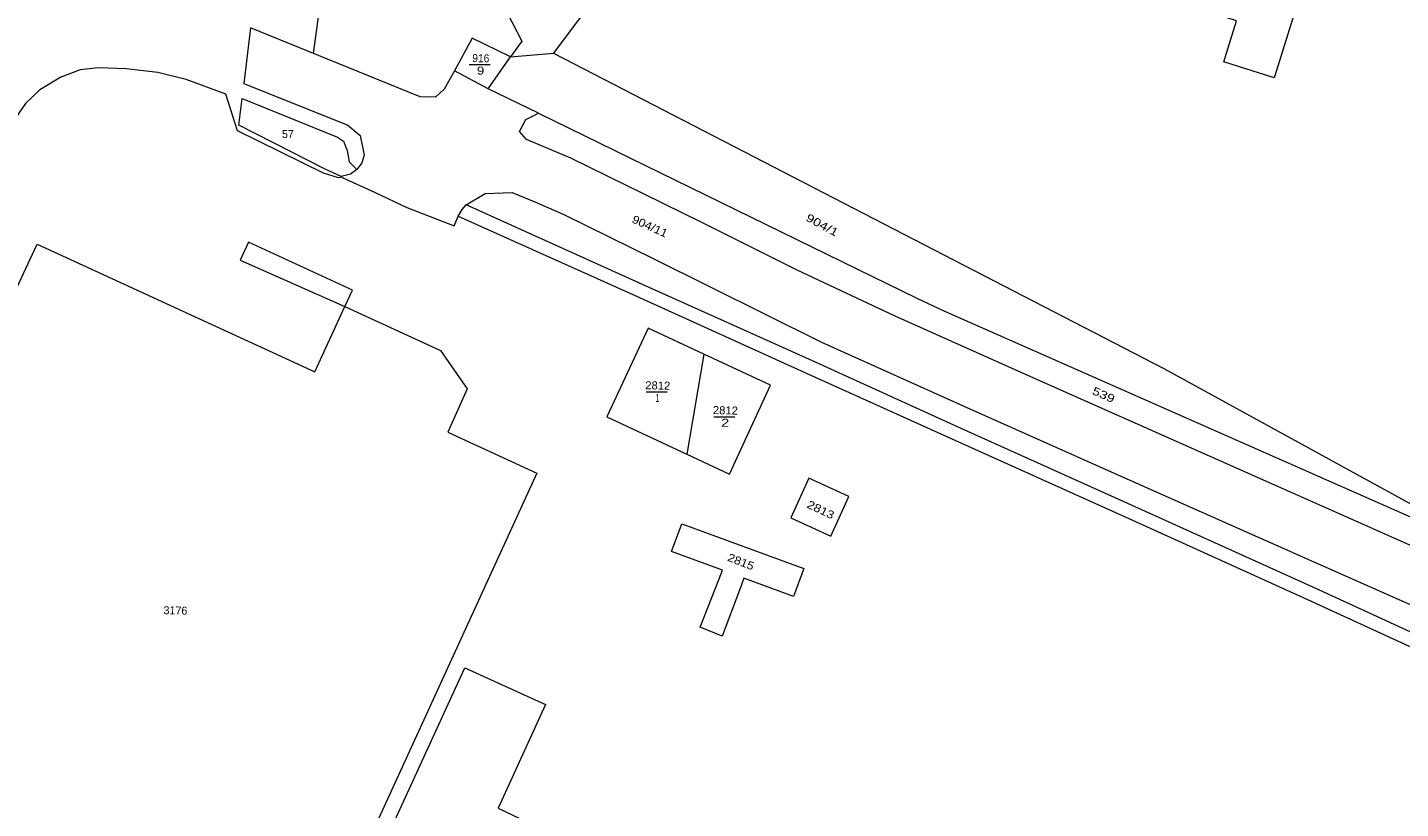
# Model space of a CAD drawing. Extents: x -843400 to -842830, y -1002860 to -1002082.
# Drawn here: x -843269.1 to -843097.6, y -1002620.7 to -1002523 of the extents above; entities that cross this region are included whole.
import ezdxf
from ezdxf.enums import TextEntityAlignment as Align

# ---------------------------------------------------------------- set-up
doc = ezdxf.new("R2010")
doc.units = 0
doc.header["$LTSCALE"] = 0.4
for name, color, linetype, lineweight in [('32', 7, 'Continuous', 13), ('34', 7, 'Continuous', 13), ('35', 7, 'Continuous', 13), ('36', 7, 'Continuous', 13), ('38', 7, 'Continuous', 13), ('43', 7, 'Continuous', 13)]:
    doc.layers.add(name, color=color, linetype=linetype, lineweight=lineweight)

msp = doc.modelspace()

# ---------------------------------------------------------------- linework, layer by layer
at = {"layer": '32'}
for points in [[(-843233.392, -1002526.274), (-843231.55, -1002512.84), (-843228.02, -1002494.21), (-843211.7, -1002440.09), (-843186.05, -1002387.15), (-843223.42, -1002493.62), (-843207.38, -1002524.72), (-843208.79, -1002526.68)], [(-843074.76, -1002421.55), (-843135.09, -1002501.71), (-843167.05, -1002477.66), (-843203.39, -1002526.24)], [(-843205.3, -1002533.74), (-843211.56, -1002530.68), (-843215.76, -1002528.45), (-843217.07, -1002530.74), (-843218.13, -1002531.75), (-843220.05, -1002531.68), (-843231.64, -1002526.99), (-843241.26, -1002523.06), (-843242.09, -1002530.04), (-843229.1, -1002535.25), (-843227.54, -1002536.54), (-843227.04, -1002539), (-843227.35, -1002539.95), (-843227.97, -1002540.79)], [(-843208.79, -1002526.68), (-843213.55, -1002524.36), (-843215.76, -1002528.45)], [(-843211.56, -1002530.68), (-843208.79, -1002526.68), (-843203.39, -1002526.24), (-843127.17, -1002565.66), (-843092.3, -1002584.79), (-843080.9, -1002591.04)], [(-843229.79, -1002541.74), (-843230.26, -1002541.8), (-843232.13, -1002541.23), (-843242.89, -1002535.94), (-843244.35, -1002531.36), (-843249.31, -1002529.54), (-843252.84, -1002528.66), (-843256.77, -1002528.18), (-843260.3, -1002528.06), (-843262.55, -1002528.32), (-843264.95, -1002529.25), (-843267.58, -1002530.82), (-843269.35, -1002532.51), (-843271.05, -1002534.95), (-843272.73, -1002537.9), (-843273.74, -1002539.98), (-843276.02, -1002546.1), (-843276.39, -1002546.03), (-843279.4, -1002552.38), (-843279.629, -1002552.744)], [(-843229.94, -1002541.67), (-843229.79, -1002541.763), (-843225.79, -1002543.62), (-843221.75, -1002545.52), (-843215.83, -1002547.82), (-843215.33, -1002546.59), (-843214.8, -1002545.76), (-843214.31, -1002545.2)], [(-843215.33, -1002546.59), (-843193.12, -1002556.57), (-843172, -1002566.13), (-843153.26, -1002574.59), (-843132, -1002584.19), (-843109.23, -1002594.52), (-843093.46, -1002601.76), (-843073.75, -1002610.86), (-843049.84, -1002621.77), (-843030.19, -1002630.96), (-843005, -1002642.63), (-842985.15, -1002651.86), (-842980.77, -1002653.89), (-842955.35, -1002665.65), (-842942.73, -1002671.51), (-842941.29, -1002671.85), (-842940.287, -1002671.376)]]:
    msp.add_lwpolyline(points, dxfattribs=at)
at = {"layer": '34'}
msp.add_line((-843213.928, -1002527.663), (-843211.332, -1002527.663), dxfattribs=at)
at = {"layer": '35'}
for p, q in [((-843191.824, -1002568.566), (-843189.228, -1002568.566)), ((-843183.374, -1002571.673), (-843180.778, -1002571.673))]:
    msp.add_line(p, q, dxfattribs=at)
at = {"layer": '36'}
msp.add_lwpolyline([(-843229.49, -1002557.91), (-843228.53, -1002555.84), (-843241.52, -1002549.85), (-843242.56, -1002552.11)], close=True, dxfattribs=at)
msp.add_lwpolyline([(-843225.82, -1002627.76), (-843214.48, -1002603.05), (-843204.43, -1002607.65), (-843210.31, -1002620.62), (-843205.72, -1002622.79)], dxfattribs=at)
at = {"layer": '38'}
for points in [[(-843122.22, -1002513.94), (-843109.79, -1002517.83), (-843113.37, -1002529.3), (-843119.68, -1002527.32), (-843118.09, -1002522.18), (-843124.19, -1002520.23)], [(-843186.76, -1002576.36), (-843181.42, -1002578.84), (-843176.3, -1002567.75), (-843184.65, -1002563.86)], [(-843171.53, -1002579.37), (-843173.78, -1002584.33), (-843168.78, -1002586.62), (-843166.52, -1002581.63)], [(-843188.65, -1002588.53), (-843187.37, -1002585.07), (-843172.12, -1002590.66), (-843173.41, -1002594.14), (-843179.62, -1002591.85), (-843180.06, -1002593.01), (-843182.34, -1002599.1), (-843185.07, -1002597.99), (-843182.73, -1002591.95), (-843182.31, -1002590.87)]]:
    msp.add_lwpolyline(points, close=True, dxfattribs=at)
for points in [[(-843276.99, -1002555.6), (-843271.63, -1002558.06), (-843267.9, -1002550.12), (-843233.22, -1002566.07), (-843229.49, -1002557.91), (-843217.51, -1002563.41), (-843214.18, -1002568.18), (-843216.63, -1002573.61), (-843205.49, -1002578.73), (-843233.93, -1002640.83), (-843246.1, -1002635.37), (-843247.52, -1002638.46), (-843254.81, -1002635.1), (-843253.51, -1002632), (-843281.23, -1002619.2), (-843296.36, -1002612.22), (-843281.484, -1002579.845), (-843280.65, -1002578.03), (-843286.12, -1002575.52)], [(-843184.65, -1002563.86), (-843191.59, -1002560.62), (-843196.74, -1002571.71), (-843186.76, -1002576.36)]]:
    msp.add_lwpolyline(points, dxfattribs=at)
at = {"layer": '43'}
for points in [[(-843242.31, -1002531.92), (-843230.4, -1002536.75), (-843229.66, -1002537.25), (-843229.17, -1002538.42), (-843228.92, -1002539.8), (-843227.97, -1002540.79), (-843228.77, -1002541.35), (-843229.94, -1002541.67), (-843231.93, -1002540.73), (-843242.71, -1002535.25)], [(-843205.3, -1002533.74), (-843157.95, -1002556.9), (-843154.65, -1002558.44), (-843080.9, -1002591.04), (-843055.92, -1002602.16), (-843057.2, -1002605.27), (-843083.34, -1002593.57), (-843099.52, -1002586.37), (-843121.47, -1002576.61), (-843143.39, -1002566.85), (-843160.74, -1002559.11), (-843172.97, -1002553.37), (-843185.06, -1002547.3), (-843201.23, -1002539.36), (-843206.78, -1002537.03), (-843207.67, -1002536.02), (-843206.85, -1002534.51)]]:
    msp.add_lwpolyline(points, close=True, dxfattribs=at)
msp.add_lwpolyline([(-843092.68, -1002600.28), (-843108.27, -1002593.1), (-843131.19, -1002582.71), (-843152.48, -1002573.13), (-843171.05, -1002564.71), (-843192.28, -1002555.13), (-843214.31, -1002545.2), (-843211.96, -1002543.79), (-843208.56, -1002543.67), (-843205.76, -1002544.83), (-843202.1, -1002546.38), (-843190.86, -1002551.95), (-843169.92, -1002562.36), (-843151.4, -1002570.7), (-843130.31, -1002580.1), (-843107.3, -1002590.3), (-843091.62, -1002597.29)], dxfattribs=at)

# ---------------------------------------------------------------- texts
at = {"layer": '34'}
for s, height, rotation, width, p in [('916', 1, 358.734, 0.95, (-843212.499, -1002527.3658)), ('9', 1, 358.734, 1.25, (-843212.5325, -1002528.9154)), ('904/11', 1, 335.525, 1.15, (-843191.5712, -1002548.3295)), ('904/1', 0.999, 331.386, 1.3, (-843170.0832, -1002548.1477))]:
    msp.add_text(s, height=height, rotation=rotation, dxfattribs=dict(at, width=width)).set_placement(p, align=Align.CENTER)
at = {"layer": '35'}
for s, rotation, width, p in [('2812', 358.734, 1.05, (-843190.395, -1002568.269)), ('1', 358.734, 0.7, (-843190.4295, -1002569.8188)), ('2812', 358.734, 1.05, (-843181.945, -1002571.376)), ('2', 358.734, 1.35, (-843181.979, -1002572.9253)), ('2813', 334.454, 1.2, (-843170.2441, -1002583.7528)), ('2815', 338.603, 1.15, (-843180.1749, -1002590.2655))]:
    msp.add_text(s, height=1, rotation=rotation, dxfattribs=dict(at, width=width)).set_placement(p, align=Align.CENTER)
msp.add_text('3176', height=1, rotation=358.734, dxfattribs=at).set_placement((-843250.647, -1002596.3893), align=Align.CENTER)
at = {"layer": '43'}
msp.add_text('57', height=1, dxfattribs=at).set_placement((-843237.333, -1002536.839))
at = {"layer": '43', "width": 1.3}
msp.add_text('539', height=1, rotation=336.153, dxfattribs=at).set_placement((-843136.226, -1002568.804))

doc.saveas('drawing.dxf')
